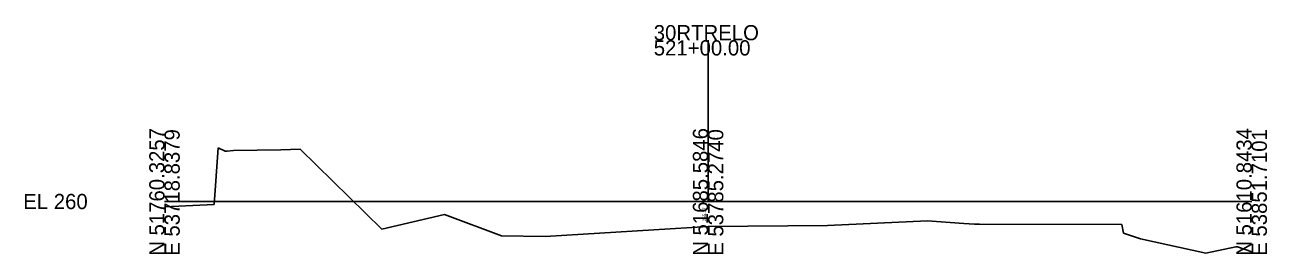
# Model space of a CAD drawing. Extents: x 12366 to 12594, y 96215 to 100251.
# Drawn here: x 12365.6 to 12594.1, y 99214.9 to 99257.2 of the extents above; entities that cross this region are included whole.
import ezdxf

# ---------------------------------------------------------------- set-up
doc = ezdxf.new("R2010")
doc.units = 0
for name, color, linetype in [('Level 10', 7, 'Continuous'), ('Level 60', 7, 'Continuous'), ('Level 63', 7, 'Continuous')]:
    doc.layers.add(name, color=color, linetype=linetype)

msp = doc.modelspace()

# ---------------------------------------------------------------- linework, layer by layer
at = {"layer": 'Level 60'}
for p, q in [((12400.46, 99224.09), (12401.17, 99234.53)), ((12401.17, 99234.53), (12402.46, 99233.91)), ((12402.46, 99233.91), (12402.86, 99233.89)), ((12402.86, 99233.89), (12404, 99234)), ((12404, 99234), (12412.7, 99234.17)), ((12412.7, 99234.17), (12416.29, 99234.25)), ((12416.29, 99234.25), (12431.3, 99219.57)), ((12391.3, 99223.63), (12400.46, 99224.09)), ((12431.3, 99219.57), (12442.8, 99222.27)), ((12442.8, 99222.27), (12453.3, 99218.3)), ((12461.3, 99218.2), (12491.3, 99220.01)), ((12491.3, 99220.01), (12513.24, 99220.21)), ((12513.24, 99220.21), (12531.69, 99221.06)), ((12531.69, 99221.06), (12538.35, 99220.57)), ((12538.35, 99220.57), (12540.31, 99220.49)), ((12540.31, 99220.49), (12541.2, 99220.48)), ((12541.2, 99220.48), (12567.44, 99220.39)), ((12567.44, 99220.39), (12567.73, 99218.81)), ((12453.3, 99218.3), (12461.3, 99218.2)), ((12567.73, 99218.81), (12570.86, 99217.78)), ((12570.86, 99217.78), (12582.88, 99215.13)), ((12582.88, 99215.13), (12588.37, 99216.3)), ((12588.37, 99216.3), (12588.69, 99216.28)), ((12588.69, 99216.28), (12591.3, 99215.35))]:
    msp.add_line(p, q, dxfattribs=at)
at = {"layer": 'Level 63'}
for p, q in [((12491.3, 99224.64), (12491.3, 99254.32)), ((12391.3, 99224.64), (12491.3, 99224.64)), ((12491.3, 99224.64), (12591.3, 99224.64))]:
    msp.add_line(p, q, dxfattribs=at)

# ---------------------------------------------------------------- texts
at = {"layer": 'Level 10'}
msp.add_text('255.37', height=0.6, rotation=90, dxfattribs=at).set_placement((12490.9, 99221.01))
at = {"layer": 'Level 63'}
for s, p in [('30RTRELO', (12481.3, 99254.32)), ('521+00.00', (12481.3, 99251.52)), ('EL 260', (12365.31, 99223.24))]:
    msp.add_text(s, height=2.8, dxfattribs=at).set_placement(p)
for s, p in [('N 51760.3257', (12391.3, 99214.64)), ('E 53718.8379', (12394.1, 99214.64)), ('N 51685.5846', (12491.3, 99214.64)), ('E 53785.2740', (12494.1, 99214.64)), ('N 51610.8434', (12591.3, 99214.64)), ('E 53851.7101', (12594.1, 99214.64))]:
    msp.add_text(s, height=2.8, rotation=90, dxfattribs=at).set_placement(p)

doc.saveas('drawing.dxf')
